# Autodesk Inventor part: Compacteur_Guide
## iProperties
Created: 2008-12
Part Number: Compacteur_Guide
Document SubType Name: Modeling
Designer: claivier
Author: claivier
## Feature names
1. Extrusion1
2. Extrusion2
3. Extrusion3
4. Extrusion4
5. Perçage1 [Hole]
6. Extrusion5
7. Chanfrein1 [Chamfer]
8. Miroir1 [Mirror]
9. Perçage2 [Hole]
10. Extrusion6
11. Perçage3 [Hole]
12. Miroir2 [Mirror]
